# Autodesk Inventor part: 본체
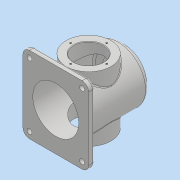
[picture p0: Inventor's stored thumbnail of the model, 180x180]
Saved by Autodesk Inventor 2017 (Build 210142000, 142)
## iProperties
Part Number: 본체
Material: 일반
Document SubType Name: Modeling
Designer: MRC
Density: 1 g/cm^3
Appearance: 기본값
Author: MRC
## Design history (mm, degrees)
sketch "스케치1"
  geometry: C1 r 50 at (0, 0); 1 further point
  constraints: 1 centre point, 1 coincident
  dimensions: "d2" = 100 diameter of C1
extrude "돌출1" new body sketch "스케치1" stored distance "d0" = 120; taper "d1" = 0 deg
sketch "스케치2"
  geometry: L1 (60, 70)-(-60, 70); L2 (-60, 70)-(-60, -70); L3 (-60, -70)-(60, -70); L4 (60, -70)-(60, 70); L5 (60, 70)-(-60, -70); L6 (-60, 70)-(60, -70); C1 r 50 at (0, 0) reference
  constraints: 12 end point, 2 midpoint, 2 parallel, 1 horizontal, 1 perpendicular
  dimensions: "d3" = 120 distance of L3.end L2.end; "d4" = 140 distance of L2.end L1.end
extrude "돌출2" join sketch "스케치2" distance "d5" = 10; taper "d6" = 0 deg
sketch "스케치3"
  geometry: C1 r 50 at (0, 0) reference; C2 r 41 at (0, 0)
  constraints: 1 centre point, 1 coincident
  dimensions: "d7" = 82 diameter of C2
extrude "돌출3" join sketch "스케치3" distance "d8" = 5; taper "d9" = 0 deg
sketch "스케치4"
  geometry: C1 r 41 at (0, 0); 1 further point
  constraints: 1 centre point, 1 coincident
  dimensions: "d10" = 82 diameter of C1
extrude "돌출4" join sketch "스케치4" stored distance "d11" = 118; taper "d12" = 0 deg
sketch "스케치5"
  geometry: C1 r 41 at (0, 0) reference; C2 r 27 at (0, 0)
  constraints: 1 centre point, 1 coincident
  dimensions: "d13" = 54 diameter of C2
extrude "돌출5" cut sketch "스케치5" stored distance "d14" = 118; taper "d15" = 0 deg
sketch "스케치6"
  geometry: C1 r 42 at (0, 0); 1 further point
  constraints: 1 centre point, 1 coincident
  dimensions: "d16" = 84 diameter of C1
extrude "돌출6" cut sketch "스케치6" distance "d17" = 112; taper "d18" = 0 deg
sketch "스케치7"
  geometry: C1 r 42 at (0, 0) reference; C2 r 27 at (0, 0)
  constraints: 1 centre point, 1 coincident
  dimensions: "d19" = 54 diameter of C2
extrude "돌출7" cut sketch "스케치7" distance "d20" = 13; taper "d21" = 0 deg
sketch "스케치8"
  geometry: 1 further point
hole "구멍1" sketch "스케치8" at (0, 33) diameter "d23" = 3.242; stored, may be unused: countersink angle "d27" = 90 deg, drill point angle "d29" = 118 deg; dims "d24" = 8, "d25" = 4, "d26" = 2, "d28" = 10
sketch "스케치9"
  geometry: C1 r 1.621 at (0, 33) reference; 1 further point
  constraints: 1 coincident
hole "구멍2" sketch "스케치9" at (0, 33) diameter "d34" = 3.242; stored, may be unused: countersink angle "d38" = 90 deg, drill point angle "d40" = 118 deg; dims "d35" = 8, "d36" = 4, "d37" = 2, "d39" = 10
sketch "스케치10" dims "d44" = 66
  geometry: C1 r 27 at (0, 0) reference; C2 r 41 at (0, 0) reference; 2 further points
  constraints: 2 horizontal alignment, 1 coincident, 2 other
hole "구멍3" sketch "스케치10" at (-33, 0) diameter "d45" = 3.242; stored, may be unused: countersink angle "d49" = 90 deg, drill point angle "d51" = 118 deg; dims "d46" = 8, "d47" = 4, "d48" = 2, "d50" = 10
fillet "모깎기1" dims "d55" = 12
fillet "모깎기2" dims "d56" = 6
fillet "모깎기3" dims "d57" = 3
chamfer "모따기1" distance "d58" = 1; stored, may be unused: second distance "d59" = 2, angle "d60" = 45 deg
node "작업 평면1"
sketch "스케치12"
  geometry: L1 (60, 58)-(60, -58) reference; 2 further points
  constraints: 1 horizontal alignment, 1 other
  dimensions: "d61" = 66 distance from line of L1 point (-6, 0)
feature "엠보싱1" sketch "스케치12" dims "d10" = 82, "d62" = 0.5, "d63" = 0
sketch "스케치13"
  geometry: A1 r 9 centre (48, 58) between (57, 58) and (48, 67) reference; A2 r 9 centre (-48, 58) between (-48, 67) and (-57, 58) reference; A3 r 9 centre (-48, -58) between (-57, -58) and (-48, -67) reference; A4 r 9 centre (48, -58) between (48, -67) and (57, -58) reference; 4 further points
  constraints: 4 coincident
hole "구멍4" sketch "스케치13" at (48, 58), (48, -58), (-48, -58), (-48, 58) diameter "d65" = 9; stored, may be unused: countersink angle "d69" = 90 deg, drill point angle "d71" = 0 deg; dims "d66" = 8, "d67" = 4, "d68" = 2, "d70" = 9
node "솔리드1"
pattern_circular "원형 패턴1" dims angle "d31" = 360 deg
pattern_circular "원형 패턴2" dims angle "d42" = 360 deg
pattern_circular "원형 패턴3" dims angle "d53" = 360 deg
